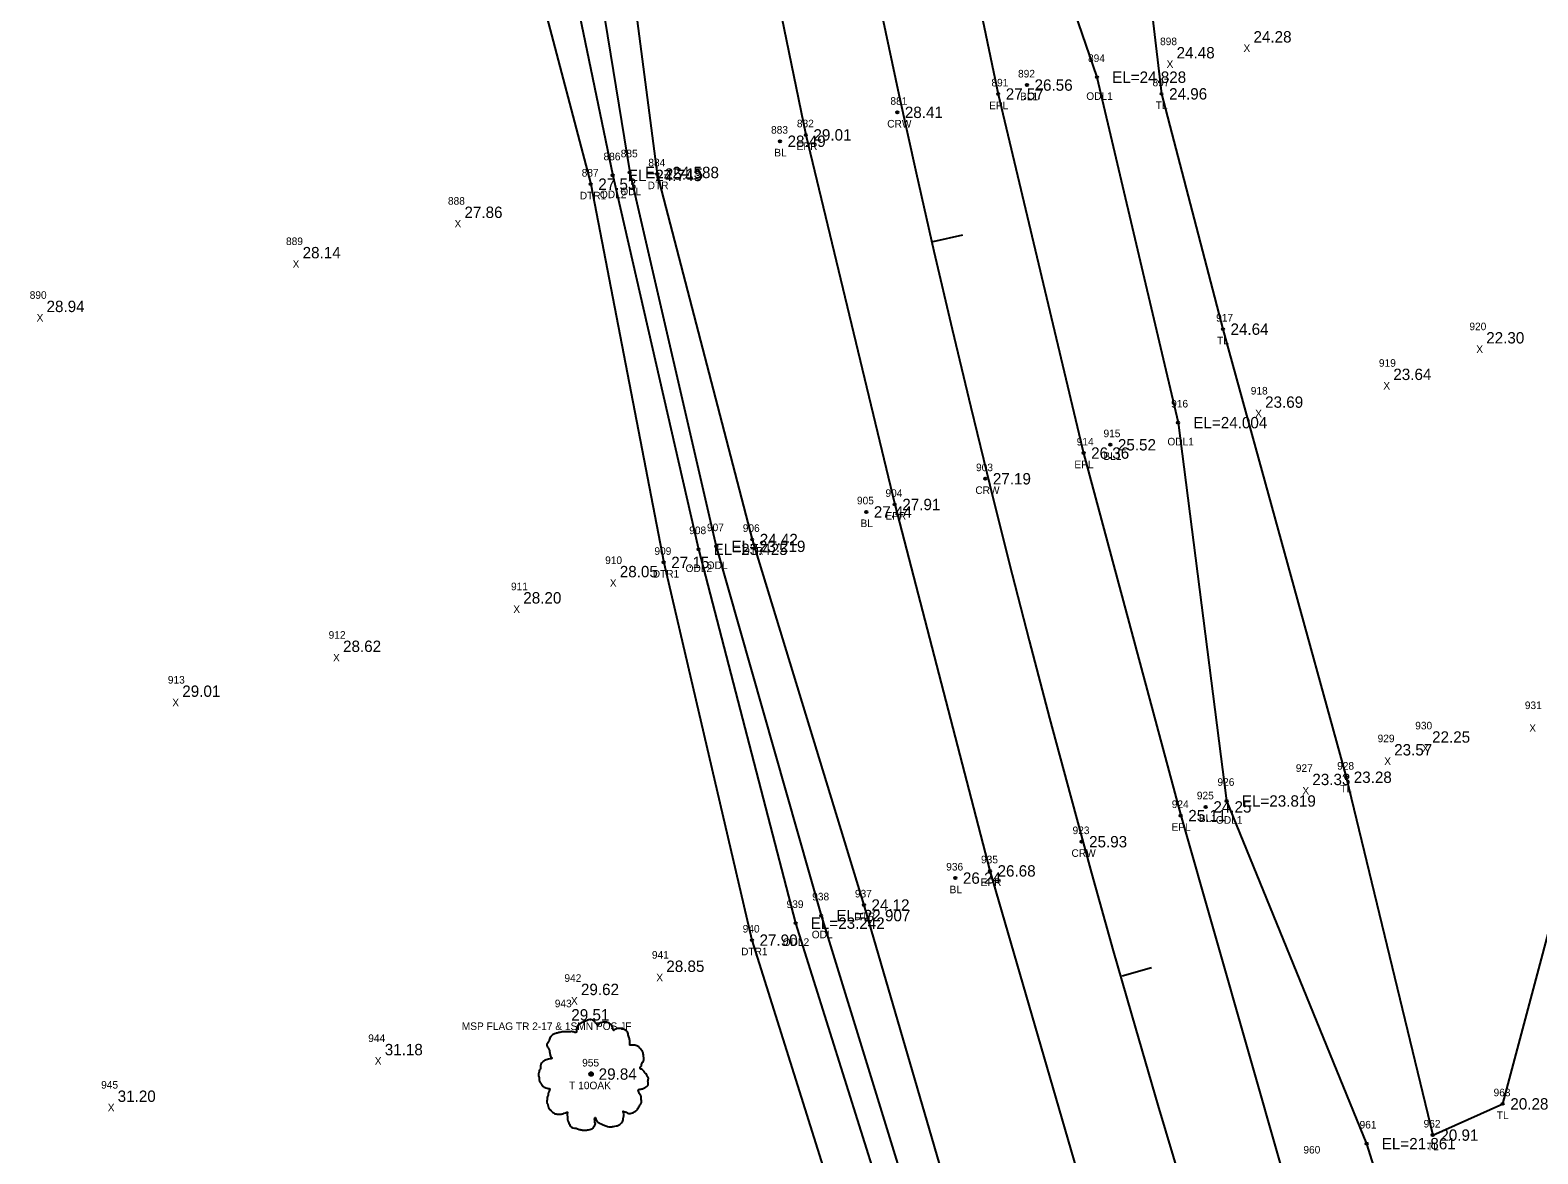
# Model space of a CAD drawing. Extents: x 2042117 to 2045853, y 303080 to 309569.
# Drawn here: x 2042769.4 to 2042968.2, y 306800.2 to 306948.4 of the extents above; entities that cross this region are included whole.
import ezdxf

# ---------------------------------------------------------------- set-up
doc = ezdxf.new("R2010")
doc.units = 0
for name, color, linetype in [('RD_DTM_BkLn_txCode', 7, 'Continuous'), ('RD_EX_H2O', 7, 'Continuous'), ('RD_EX_H2O_txCode', 7, 'Continuous'), ('RD_EX_Misc_txCode', 7, 'Continuous'), ('RD_EX_Road', 7, 'Continuous'), ('RD_EX_Road_txCode', 7, 'Continuous'), ('RD_EX_TX_H2O_ELEV', 7, 'Continuous'), ('RD_EX_TX_Misc_ELEV', 7, 'Continuous'), ('RD_EX_TX_Road_ELEV', 7, 'Continuous'), ('RD_EX_TX_VEG_ELEV', 7, 'Continuous'), ('RD_EX_VEG', 7, 'Continuous'), ('RD_EX_VEG_txCode', 7, 'Continuous'), ('RD_HC_Cl', 7, 'Continuous'), ('RD_HC_Data_Tic', 7, 'Continuous'), ('RD_HC_Survey_ELEV', 7, 'Continuous'), ('RD_HC_Survey_txCode', 7, 'Continuous'), ('RD_SMD_Locator', 7, 'Continuous')]:
    doc.layers.add(name, color=color, linetype=linetype)

msp = doc.modelspace()

# ---------------------------------------------------------------- linework, layer by layer
at = {"layer": 'RD_EX_H2O'}
for points in [[(2042865.43, 307427.05), (2042866.84, 307378.87), (2042866.82, 307329.93), (2042876.23, 307282.16), (2042878.43, 307232.86), (2042875.08, 307184.77), (2042887.19, 307136.65), (2042884.32, 307120.02), (2042882.74, 307087.49), (2042892.51, 307039.16), (2042896.41, 306990.42), (2042899.37, 306973.37), (2042910.05, 306942.23), (2042920.75, 306896.67), (2042927.15, 306846.78), (2042945.6, 306801.59), (2042960.32, 306754.61), (2042976.65, 306708.74), (2042994.63, 306662.76), (2043013.3, 306616.98), (2043029.17, 306571.91), (2043050.77, 306528.53)], [(2042809.74, 307126.16), (2042806.56, 307122.63), (2042790.31, 307116.78), (2042788.49, 307114.78), (2042791.89, 307113.57), (2042804.81, 307114.94), (2042810.25, 307075.93), (2042820.25, 307025.92), (2042830.4, 306977.21), (2042843.29, 306928.12), (2042852.91, 306878.24), (2042864.55, 306828.43), (2042879.23, 306781.72), (2042889.45, 306748.73), (2042886.16, 306741.98), (2042888.34, 306727.94), (2042896.13, 306676.35), (2042885.67, 306665.43), (2042857.25, 306612.72)], [(2042809.74, 307126.16), (2042815.01, 307124.31), (2042821.79, 307118.99), (2042825.8, 307110.2), (2042827.88, 307100.21), (2042830.08, 307078.71), (2042836.25, 307029.11), (2042845.48, 306980.04), (2042852.07, 306929.46), (2042864.58, 306881.26), (2042879.31, 306833.06), (2042893.37, 306784.78), (2042908.76, 306736.23), (2042928.77, 306689.39), (2042938.94, 306669.11)], [(2042812.2, 307117.75), (2042817.66, 307076.99), (2042828.97, 307027.39), (2042840.42, 306978.95), (2042848.44, 306929.66), (2042859.84, 306880.36), (2042873.68, 306831.67), (2042888.54, 306783.43), (2042900.59, 306749.27), (2042902.9, 306733.67), (2042926.04, 306688.21), (2042936.45, 306668.37), (2042947.44, 306643.99), (2042966.18, 306597.91), (2042985.34, 306551.14), (2042987.61, 306538.59)], [(2042810.02, 307117.36), (2042813.87, 307076.18), (2042825.65, 307027), (2042835.99, 306978.45), (2042846.19, 306929.27), (2042857.5, 306879.97), (2042870.3, 306830.67), (2042885.37, 306782.68), (2042895.57, 306748.28), (2042892.03, 306740.63), (2042891.66, 306731.27), (2042905.95, 306680.58), (2042906.87, 306643.18), (2042864.97, 306605.63)]]:
    msp.add_lwpolyline(points, dxfattribs=at)
at = {"layer": 'RD_EX_Road'}
for points in [[(2042828.36, 307428.87), (2042826.99, 307378.91), (2042826.88, 307329.29), (2042828.01, 307279.82), (2042830.5, 307230.24), (2042834.09, 307180.37), (2042835.89, 307157.73), (2042833.55, 307154.38), (2042836.54, 307132.83), (2042837.33, 307130.11), (2042837.64, 307128.77), (2042839.22, 307126.16), (2042844.98, 307081.33), (2042852.86, 307032.13), (2042861.74, 306982.99), (2042871.66, 306934.62), (2042883.38, 306885.88), (2042895.94, 306837.56), (2042909.76, 306789.89)], [(2042855.03, 307427.78), (2042853.64, 307379.19), (2042853.31, 307329.44), (2042854.43, 307281.38), (2042857.15, 307232.07), (2042860.27, 307183.35), (2042865.16, 307133.89), (2042871.37, 307085.7), (2042878.53, 307037.13), (2042886.97, 306988.21), (2042897.02, 306940.01), (2042908.28, 306892.66), (2042921.09, 306844.85), (2042934.41, 306798.2)]]:
    msp.add_lwpolyline(points, dxfattribs=at)
at = {"layer": 'RD_EX_VEG'}
msp.add_lwpolyline([(2042885.61, 307482.85), (2042881.1, 307379.92), (2042880.44, 307351.7), (2042880.19, 307284.9), (2042884.99, 307224.08), (2042886.48, 307195.22), (2042890.83, 307127.55), (2042909.45, 307007.86), (2042916.1, 306960.95), (2042918.56, 306940.03), (2042926.66, 306909), (2042942.91, 306849.91), (2042954.33, 306802.72), (2042963.56, 306806.84), (2042974.33, 306847.25), (2043002.07, 306860.54), (2043032.14, 306846.51)], dxfattribs=at)
for centre, radius in [((2042843.34, 306810.77), 0.25), ((2042843.33, 306810.75), 0.0001)]:
    msp.add_circle(centre, radius, dxfattribs=at)
for points in [[(2042843.47, 306817.93), (2042843.17, 306817.96), (2042842.85, 306817.86), (2042842.6, 306817.76), (2042842.37, 306817.68), (2042842.15, 306817.58), (2042841.85, 306817.41), (2042841.62, 306817.21), (2042841.5, 306816.96), (2042841.45, 306816.74), (2042841.4, 306816.46), (2042841.4, 306816.29), (2042841.27, 306816.26), (2042841.12, 306816.29), (2042840.87, 306816.36), (2042840.62, 306816.36), (2042840.37, 306816.36), (2042840.02, 306816.34), (2042839.67, 306816.34), (2042839.4, 306816.29), (2042839.07, 306816.24), (2042838.7, 306816.11), (2042838.35, 306815.99), (2042838.05, 306815.74), (2042837.8, 306815.26), (2042837.67, 306814.91), (2042837.52, 306814.66), (2042837.67, 306814.21), (2042837.85, 306813.86), (2042837.87, 306813.66), (2042837.95, 306813.24), (2042838.05, 306813.01), (2042838.17, 306812.81), (2042838.1, 306812.79), (2042837.72, 306812.74), (2042837.42, 306812.64), (2042837, 306812.41), (2042836.77, 306812.19), (2042836.67, 306811.86), (2042836.65, 306811.51), (2042836.55, 306811.31), (2042836.47, 306811.04), (2042836.45, 306810.96), (2042836.4, 306810.64), (2042836.5, 306810.19), (2042836.52, 306809.84), (2042836.65, 306809.61), (2042836.8, 306809.44), (2042836.97, 306809.19), (2042837.37, 306808.96), (2042837.7, 306808.86), (2042837.9, 306808.84), (2042837.72, 306808.34), (2042837.67, 306807.99), (2042837.55, 306807.59), (2042837.55, 306807.51), (2042837.5, 306807.04), (2042837.65, 306806.71), (2042837.72, 306806.34), (2042837.9, 306806.11), (2042838.17, 306805.82), (2042838.5, 306805.59), (2042839, 306805.47), (2042839.4, 306805.49), (2042839.97, 306805.67), (2042840.22, 306805.74), (2042840.2, 306805.57), (2042840.22, 306805.19), (2042840.22, 306804.77), (2042840.37, 306804.44), (2042840.47, 306804.17), (2042840.62, 306803.92), (2042840.95, 306803.69), (2042841.35, 306803.62), (2042841.77, 306803.47), (2042842.22, 306803.39), (2042842.72, 306803.37), (2042843.32, 306803.52), (2042843.6, 306803.64), (2042843.7, 306803.82), (2042843.9, 306804.19), (2042843.85, 306804.42), (2042843.87, 306805.02), (2042843.97, 306804.84), (2042844.15, 306804.49), (2042844.65, 306804.19), (2042845.05, 306804.02), (2042845.52, 306803.87), (2042845.82, 306803.79), (2042846.29, 306803.87), (2042846.67, 306803.94), (2042847.04, 306804.07), (2042847.34, 306804.34), (2042847.52, 306804.62), (2042847.57, 306804.89), (2042847.64, 306805.27), (2042847.69, 306805.44)], [(2042847.69, 306805.44), (2042847.62, 306805.62), (2042847.57, 306805.87), (2042847.64, 306805.84), (2042847.82, 306805.79), (2042848.09, 306805.67), (2042848.32, 306805.59), (2042848.64, 306805.62), (2042848.92, 306805.72), (2042849.37, 306805.99), (2042849.64, 306806.46), (2042849.92, 306806.86), (2042849.99, 306807.19), (2042849.94, 306807.41), (2042849.92, 306807.91), (2042849.72, 306808.16), (2042849.67, 306808.29), (2042849.57, 306808.69), (2042849.64, 306808.74), (2042849.92, 306808.79), (2042850.29, 306808.91), (2042850.57, 306809.04), (2042850.79, 306809.21), (2042850.87, 306809.44), (2042850.84, 306809.84), (2042850.89, 306810.24), (2042850.82, 306810.39), (2042850.72, 306810.54), (2042850.64, 306810.74), (2042850.49, 306810.89), (2042850.39, 306811.04), (2042850.29, 306811.14), (2042850.17, 306811.29), (2042849.99, 306811.41), (2042849.84, 306811.46), (2042849.79, 306811.61), (2042849.94, 306811.81), (2042849.99, 306811.91), (2042850.02, 306812.14), (2042850.24, 306812.49), (2042850.29, 306812.89), (2042850.24, 306813.31), (2042850.19, 306813.59), (2042850.04, 306813.86), (2042849.84, 306814.11), (2042849.72, 306814.29), (2042849.54, 306814.41), (2042849.22, 306814.54), (2042848.97, 306814.59), (2042848.62, 306814.59), (2042848.42, 306814.64), (2042848.44, 306814.69), (2042848.44, 306814.84), (2042848.44, 306815.11), (2042848.37, 306815.56), (2042848.22, 306816.06), (2042848.22, 306816.09), (2042848.12, 306816.34), (2042847.89, 306816.54), (2042847.72, 306816.64), (2042847.52, 306816.76), (2042847.27, 306816.79), (2042846.97, 306816.79), (2042846.69, 306816.74), (2042846.49, 306816.64), (2042846.32, 306816.51), (2042846.24, 306816.66), (2042846.14, 306816.96), (2042846.09, 306817.11), (2042845.94, 306817.29), (2042845.72, 306817.48), (2042845.27, 306817.61), (2042844.65, 306817.53), (2042844.35, 306817.34), (2042844.2, 306817.16), (2042844.15, 306817.29), (2042843.95, 306817.48), (2042843.85, 306817.66), (2042843.67, 306817.78), (2042843.52, 306817.88), (2042843.42, 306817.93)]]:
    msp.add_spline(points, degree=3, dxfattribs=at)
at = {"layer": 'RD_HC_Cl'}
msp.add_arc((2044751.25, 307348.43), 1911.29, 137.68184, 219.86836, dxfattribs=at)
at = {"layer": 'RD_HC_Data_Tic'}
for p, q in [((2042888.47, 306920.55), (2042892.36, 306921.45)), ((2042913.39, 306823.72), (2042917.24, 306824.82))]:
    msp.add_line(p, q, dxfattribs=at)
at = {"layer": 'RD_SMD_Locator'}
for centre in [(2042900.82, 306941.19), (2042910.05, 306942.23), (2042897.02, 306940.01), (2042918.56, 306940.03), (2042883.71, 306937.59), (2042871.66, 306934.62), (2042868.25, 306933.78), (2042846.19, 306929.27), (2042848.44, 306929.66), (2042852.07, 306929.46), (2042843.29, 306928.12), (2042926.66, 306909), (2042920.75, 306896.67), (2042908.28, 306892.66), (2042911.81, 306893.75), (2042895.32, 306889.27), (2042879.62, 306884.9), (2042883.38, 306885.88), (2042864.58, 306881.26), (2042857.5, 306879.97), (2042859.84, 306880.36), (2042852.91, 306878.24), (2042942.91, 306849.91), (2042924.4, 306846), (2042927.15, 306846.78), (2042921.09, 306844.85), (2042908.01, 306841.41), (2042895.94, 306837.56), (2042891.37, 306836.61), (2042879.31, 306833.06), (2042873.68, 306831.67), (2042870.3, 306830.67), (2042864.55, 306828.43), (2042843.34, 306810.77), (2042963.56, 306806.84), (2042945.6, 306801.59), (2042954.33, 306802.72)]:
    msp.add_circle(centre, 0.15, dxfattribs=at)

# ---------------------------------------------------------------- texts
at = {"layer": 'RD_DTM_BkLn_txCode'}
for s, p in [('892', (2042899.64, 306942.19)), ('BL1', (2042899.9, 306939.19)), ('883', (2042867.07, 306934.78)), ('BL', (2042867.5, 306931.78)), ('915', (2042910.91, 306894.75)), ('BL1', (2042910.89, 306891.75)), ('905', (2042878.4, 306885.9)), ('BL', (2042878.86, 306882.9)), ('925', (2042923.22, 306847)), ('BL1', (2042923.48, 306844)), ('936', (2042890.17, 306837.61)), ('BL', (2042890.62, 306834.61)), ('960', (2042937.27, 306800.29))]:
    msp.add_text(s, height=1, dxfattribs=at).set_placement(p)
at = {"layer": 'RD_EX_H2O_txCode'}
for s, p in [('894', (2042908.87, 306944.23)), ('ODL1', (2042908.64, 306939.23)), ('885', (2042847.25, 306931.66)), ('886', (2042844.98, 306931.27)), ('884', (2042850.89, 306930.46)), ('887', (2042842.1, 306929.12)), ('DTR1', (2042841.85, 306926.12)), ('ODL2', (2042844.5, 306926.27)), ('ODL', (2042847.19, 306926.66)), ('DTR', (2042850.8, 306927.46)), ('916', (2042919.83, 306898.67)), ('ODL1', (2042919.34, 306893.67)), ('908', (2042856.28, 306881.97)), ('907', (2042858.62, 306882.36)), ('906', (2042863.34, 306882.26)), ('909', (2042851.69, 306879.24)), ('DTR', (2042863.32, 306879.26)), ('DTR1', (2042851.47, 306876.24)), ('ODL2', (2042855.8, 306876.97)), ('ODL', (2042858.59, 306877.36)), ('926', (2042925.94, 306848.78)), ('ODL1', (2042925.74, 306843.78)), ('939', (2042869.12, 306832.67)), ('938', (2042872.5, 306833.67)), ('937', (2042878.13, 306834.06)), ('DTR', (2042878.04, 306831.06)), ('940', (2042863.33, 306829.43)), ('ODL', (2042872.44, 306828.67)), ('DTR1', (2042863.12, 306826.43)), ('ODL2', (2042868.61, 306827.67)), ('961', (2042944.68, 306803.59))]:
    msp.add_text(s, height=1, dxfattribs=at).set_placement(p)
at = {"layer": 'RD_EX_Misc_txCode'}
for s, p in [('898', (2042918.37, 306946.45)), ('X', (2042929.37, 306945.55)), ('X', (2042919.23, 306943.45)), ('888', (2042824.46, 306925.41)), ('X', (2042825.33, 306922.41)), ('889', (2042803.11, 306920.09)), ('X', (2042803.98, 306917.09)), ('890', (2042769.31, 306913)), ('X', (2042770.22, 306910)), ('920', (2042959.16, 306908.86)), ('X', (2042960.07, 306905.86)), ('919', (2042947.23, 306904.04)), ('918', (2042930.33, 306900.38)), ('X', (2042947.81, 306901.04)), ('X', (2042930.91, 306897.38)), ('910', (2042845.19, 306878.03)), ('911', (2042832.78, 306874.57)), ('X', (2042845.81, 306875.03)), ('X', (2042833.08, 306871.57)), ('912', (2042808.73, 306868.18)), ('X', (2042809.31, 306865.18)), ('913', (2042787.53, 306862.26)), ('X', (2042788.11, 306859.26)), ('931', (2042966.47, 306858.9)), ('930', (2042952.02, 306856.22)), ('929', (2042947.06, 306854.53)), ('X', (2042967.06, 306855.9)), ('X', (2042952.92, 306853.22)), ('927', (2042936.27, 306850.62)), ('X', (2042947.93, 306851.53)), ('X', (2042937.14, 306847.62)), ('941', (2042851.36, 306825.99)), ('942', (2042839.82, 306822.93)), ('X', (2042851.94, 306822.99)), ('943', (2042838.55, 306819.58)), ('X', (2042840.68, 306819.93)), ('MSP FLAG TR 2-17 & 1SMN POS JF', (2042826.29, 306816.58)), ('944', (2042813.95, 306815)), ('X', (2042814.81, 306812)), ('945', (2042778.73, 306808.85)), ('X', (2042779.6, 306805.85))]:
    msp.add_text(s, height=1, dxfattribs=at).set_placement(p)
at = {"layer": 'RD_EX_Road_txCode'}
for s, p in [('891', (2042896.13, 306941.01)), ('EPL', (2042895.82, 306938.01)), ('882', (2042870.48, 306935.62)), ('EPR', (2042870.44, 306932.62)), ('914', (2042907.38, 306893.66)), ('EPL', (2042907.07, 306890.66)), ('904', (2042882.16, 306886.88)), ('EPR', (2042882.15, 306883.88)), ('924', (2042919.91, 306845.85)), ('EPL', (2042919.88, 306842.85)), ('935', (2042894.76, 306838.56)), ('EPR', (2042894.71, 306835.56))]:
    msp.add_text(s, height=1, dxfattribs=at).set_placement(p)
at = {"layer": 'RD_EX_TX_H2O_ELEV'}
for s, p in [('EL=24.828', (2042912.05, 306941.48)), ('27.53', (2042844.29, 306927.37)), ('EL=24.743', (2042848.19, 306928.52)), ('EL=24.588', (2042850.44, 306928.91)), ('25.15', (2042853.07, 306928.71)), ('EL=24.004', (2042922.75, 306895.92)), ('EL=23.219', (2042861.84, 306879.61)), ('24.42', (2042865.58, 306880.51)), ('27.15', (2042853.91, 306877.49)), ('EL=23.425', (2042859.5, 306879.22)), ('EL=23.819', (2042929.15, 306846.03)), ('24.12', (2042880.31, 306832.31)), ('EL=23.242', (2042872.3, 306829.92)), ('EL=22.907', (2042875.68, 306830.92)), ('27.90', (2042865.55, 306827.68)), ('EL=21.861', (2042947.6, 306800.84))]:
    msp.add_text(s, height=1.5, dxfattribs=at).set_placement(p)
at = {"layer": 'RD_EX_TX_Misc_ELEV'}
for s, p in [('24.28', (2042930.69, 306946.8)), ('24.48', (2042920.55, 306944.7)), ('26.56', (2042901.82, 306940.44)), ('28.49', (2042869.25, 306933.03)), ('27.86', (2042826.64, 306923.66)), ('28.14', (2042805.3, 306918.34)), ('28.94', (2042771.53, 306911.25)), ('22.30', (2042961.38, 306907.11)), ('23.64', (2042949.13, 306902.29)), ('23.69', (2042932.22, 306898.63)), ('25.52', (2042912.81, 306893)), ('27.44', (2042880.62, 306884.15)), ('28.05', (2042847.12, 306876.28)), ('28.20', (2042834.4, 306872.82)), ('28.62', (2042810.63, 306866.43)), ('29.01', (2042789.43, 306860.51)), ('22.25', (2042954.24, 306854.47)), ('23.57', (2042949.24, 306852.78)), ('23.33', (2042938.45, 306848.87)), ('24.25', (2042925.4, 306845.25)), ('26.24', (2042892.37, 306835.86)), ('28.85', (2042853.26, 306824.24)), ('29.62', (2042842, 306821.18)), ('29.51', (2042840.73, 306817.83)), ('31.18', (2042816.13, 306813.25)), ('31.20', (2042780.91, 306807.1))]:
    msp.add_text(s, height=1.5, dxfattribs=at).set_placement(p)
at = {"layer": 'RD_EX_TX_Road_ELEV'}
for s, p in [('27.57', (2042898.02, 306939.26)), ('29.01', (2042872.66, 306933.87)), ('26.36', (2042909.28, 306891.91)), ('27.91', (2042884.38, 306885.13)), ('25.11', (2042922.09, 306844.1)), ('26.68', (2042896.94, 306836.81))]:
    msp.add_text(s, height=1.5, dxfattribs=at).set_placement(p)
at = {"layer": 'RD_EX_TX_VEG_ELEV'}
for s, p in [('24.96', (2042919.56, 306939.28)), ('24.64', (2042927.66, 306908.25)), ('23.28', (2042943.91, 306849.16)), ('29.84', (2042844.34, 306810.02)), ('20.28', (2042964.56, 306806.09)), ('20.91', (2042955.33, 306801.97))]:
    msp.add_text(s, height=1.5, dxfattribs=at).set_placement(p)
at = {"layer": 'RD_EX_VEG_txCode'}
for s, p in [('897', (2042917.38, 306941.03)), ('TL', (2042917.79, 306938.03)), ('917', (2042925.76, 306910)), ('TL', (2042925.89, 306907)), ('928', (2042941.72, 306850.91)), ('TL', (2042942.13, 306847.91)), ('955', (2042842.16, 306811.77)), ('T 10OAK', (2042840.45, 306808.77)), ('963', (2042962.35, 306807.84)), ('TL', (2042962.78, 306804.84)), ('962', (2042953.12, 306803.72)), ('TL', (2042953.56, 306800.72))]:
    msp.add_text(s, height=1, dxfattribs=at).set_placement(p)
at = {"layer": 'RD_HC_Survey_ELEV'}
for s, p in [('28.41', (2042884.71, 306936.84)), ('27.19', (2042896.32, 306888.52)), ('25.93', (2042909.01, 306840.66))]:
    msp.add_text(s, height=1.5, dxfattribs=at).set_placement(p)
at = {"layer": 'RD_HC_Survey_txCode'}
for s, p in [('881', (2042882.81, 306938.59)), ('CRW', (2042882.39, 306935.59)), ('903', (2042894.1, 306890.27)), ('CRW', (2042894.01, 306887.27)), ('923', (2042906.83, 306842.41)), ('CRW', (2042906.69, 306839.41))]:
    msp.add_text(s, height=1, dxfattribs=at).set_placement(p)

doc.saveas('drawing.dxf')
